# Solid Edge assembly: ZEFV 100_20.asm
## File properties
Title: Zylinder
Author: bmolnar
Template: iso metric assembly.asm
Last saved by: bmolnar
Revision: 8
Application: Solid Edge
Username: bmolnar
Dokumentum tartalom típus: 1
Document Number: ZEFV 100/20
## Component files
Kit_2.par
Profilrohr.par
Kolbenstange.par
Kit_1.par
Mutter.par
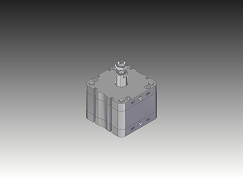
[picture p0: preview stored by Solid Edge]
